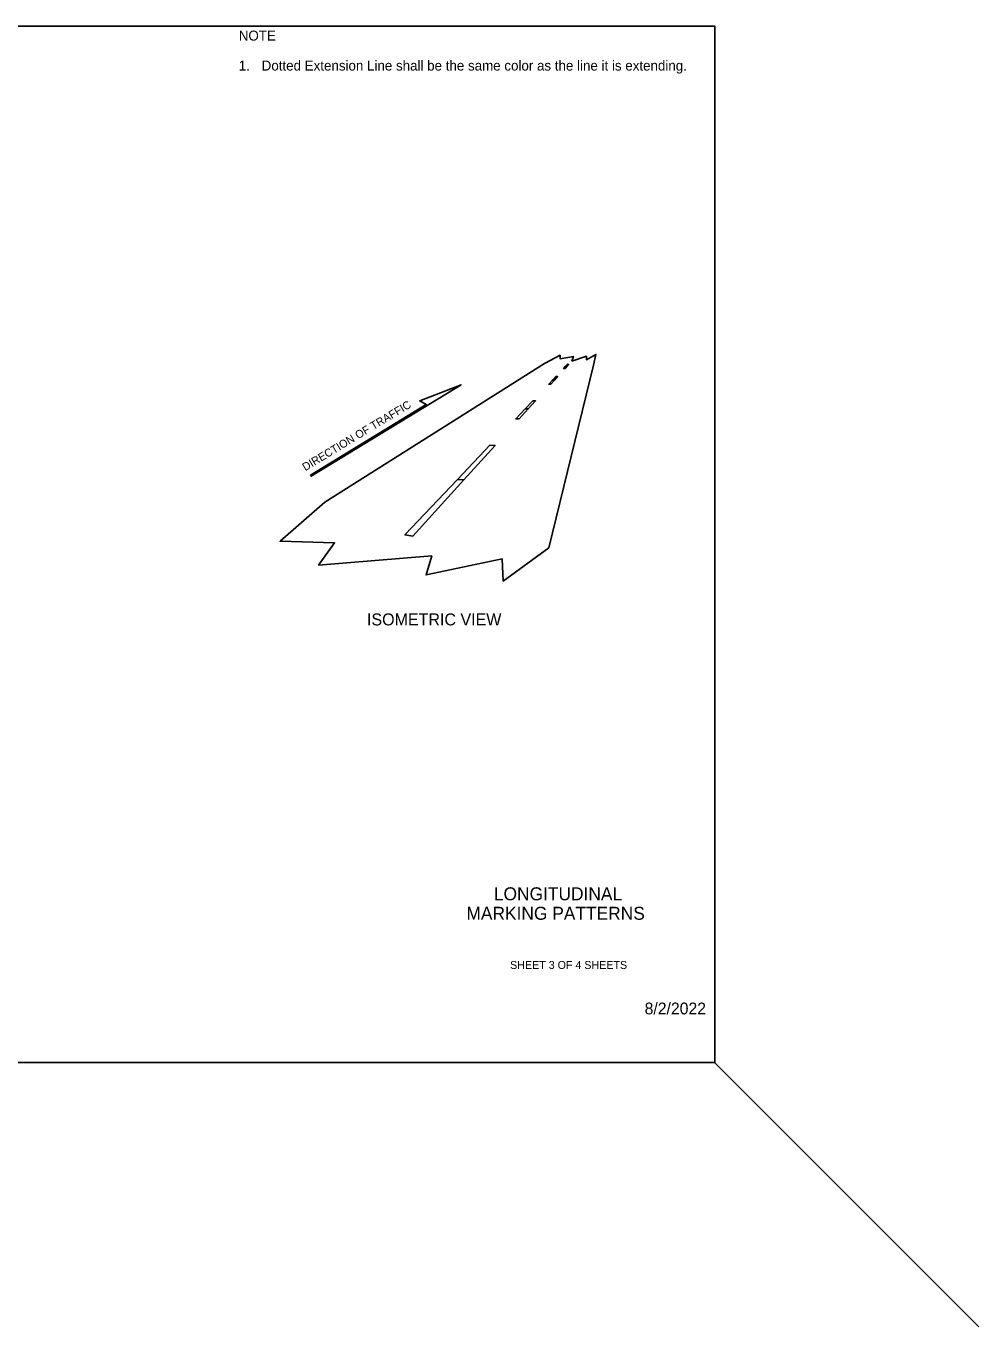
# Model space of a CAD drawing. Extents: x 99754 to 103681, y 99470 to 110996.
# Drawn here: x 101772 to 103681, y 105345 to 107951 of the extents above; entities that cross this region are included whole.
import ezdxf

# ---------------------------------------------------------------- set-up
doc = ezdxf.new("R2010")
doc.units = 0
for name, color, linetype in [('Level 1', 7, 'Continuous'), ('Level 12', 7, 'Continuous'), ('Level 14', 7, 'Continuous'), ('Level 15', 7, 'Continuous'), ('Level 16', 7, 'Continuous'), ('Level 20', 7, 'Continuous'), ('Level 23', 7, 'Continuous'), ('Level 4', 7, 'Continuous'), ('Level 60', 7, 'Continuous'), ('Level 62', 7, 'Continuous')]:
    doc.layers.add(name, color=color, linetype=linetype)

msp = doc.modelspace()

# ---------------------------------------------------------------- linework, layer by layer
at = {"layer": 'Level 1'}
msp.add_line((103151, 105875.5), (103681.3, 105345.2), dxfattribs=at)
msp.add_line((103151, 105875.5), (103681.3, 105345.2), dxfattribs=at)
msp.add_lwpolyline([(99863, 105875), (103152, 105875), (103152, 107951), (99863, 107951)], close=True, dxfattribs=at)
at = {"layer": 'Level 12'}
for p, q in [((102371, 106997.2), (102811.2, 107274.7)), ((102371, 106997.2), (102811.2, 107274.7)), ((102819.5, 106905.6), (102909, 107272)), ((102819.5, 106905.6), (102909, 107272))]:
    msp.add_line(p, q, dxfattribs=at)
at = {"layer": 'Level 14'}
for points in [[(102856.1, 107269.4), (102853.1, 107269.5), (102856.8, 107273.4), (102859.6, 107273.3), (102856.1, 107269.4)], [(102856.1, 107269.4), (102853.1, 107269.5), (102856.8, 107273.4), (102859.6, 107273.3), (102856.1, 107269.4)], [(102856.1, 107269.4), (102853.1, 107269.5), (102856.8, 107273.4), (102859.6, 107273.3), (102856.1, 107269.4)], [(102856.1, 107269.4), (102853.1, 107269.5), (102856.8, 107273.4), (102859.6, 107273.3), (102856.1, 107269.4)], [(102830.9, 107241.7), (102826.9, 107241.8), (102833.5, 107248.8), (102837.2, 107248.7), (102830.9, 107241.7)], [(102830.9, 107241.7), (102826.9, 107241.8), (102833.5, 107248.8), (102837.2, 107248.7), (102830.9, 107241.7)], [(102830.9, 107241.7), (102826.9, 107241.8), (102833.5, 107248.8), (102837.2, 107248.7), (102830.9, 107241.7)], [(102830.9, 107241.7), (102826.9, 107241.8), (102833.5, 107248.8), (102837.2, 107248.7), (102830.9, 107241.7)], [(102778.3, 107183.9), (102772.3, 107184.2), (102787.5, 107200.2), (102793, 107200), (102778.3, 107183.9)], [(102778.3, 107183.9), (102772.3, 107184.2), (102787.5, 107200.2), (102793, 107200), (102778.3, 107183.9)], [(102778.3, 107183.9), (102772.3, 107184.2), (102787.5, 107200.2), (102793, 107200), (102778.3, 107183.9)], [(102778.3, 107183.9), (102772.3, 107184.2), (102787.5, 107200.2), (102793, 107200), (102778.3, 107183.9)], [(102649.1, 107041.7), (102636.6, 107043), (102701.6, 107111.6), (102711.9, 107110.8), (102649.1, 107041.7)], [(102649.1, 107041.7), (102636.6, 107043), (102701.6, 107111.6), (102711.9, 107110.8), (102649.1, 107041.7)], [(102649.1, 107041.7), (102636.6, 107043), (102701.6, 107111.6), (102711.9, 107110.8), (102649.1, 107041.7)], [(102649.1, 107041.7), (102636.6, 107043), (102701.6, 107111.6), (102711.9, 107110.8), (102649.1, 107041.7)]]:
    msp.add_lwpolyline(points, dxfattribs=at)
at = {"layer": 'Level 16'}
for points in [[(102852.1, 107265.1), (102849, 107265.2), (102853.1, 107269.5), (102856.1, 107269.4), (102852.1, 107265.1)], [(102852.1, 107265.1), (102849, 107265.2), (102853.1, 107269.5), (102856.1, 107269.4), (102852.1, 107265.1)], [(102823.5, 107233.6), (102819.3, 107233.8), (102826.9, 107241.8), (102830.9, 107241.7), (102823.5, 107233.6)], [(102823.5, 107233.6), (102819.3, 107233.8), (102826.9, 107241.8), (102830.9, 107241.7), (102823.5, 107233.6)], [(102760.1, 107163.9), (102753.4, 107164.2), (102772.3, 107184.2), (102778.3, 107183.9), (102760.1, 107163.9)], [(102760.1, 107163.9), (102753.4, 107164.2), (102772.3, 107184.2), (102778.3, 107183.9), (102760.1, 107163.9)], [(102547.1, 106929.5), (102531.3, 106931.8), (102636.6, 107043), (102649.1, 107041.7), (102547.1, 106929.5)], [(102547.1, 106929.5), (102531.3, 106931.8), (102636.6, 107043), (102649.1, 107041.7), (102547.1, 106929.5)]]:
    msp.add_lwpolyline(points, dxfattribs=at)
at = {"layer": 'Level 20'}
msp.add_lwpolyline([(102342.4, 107051.3), (102574.1, 107193), (102561, 107200.1), (102643.7, 107232.6), (102343.7, 107049.2)], close=True, dxfattribs=at)
at = {"layer": 'Level 23'}
for p, q in [((102856.1, 107269.4), (102853.1, 107269.5)), ((102853.1, 107269.5), (102856.1, 107269.4)), ((102856.1, 107269.4), (102853.1, 107269.5)), ((102853.1, 107269.5), (102856.1, 107269.4)), ((102826.9, 107241.8), (102833.5, 107248.8)), ((102826.9, 107241.8), (102833.5, 107248.8)), ((102830.9, 107241.7), (102826.9, 107241.8)), ((102826.9, 107241.8), (102830.9, 107241.7)), ((102830.9, 107241.7), (102826.9, 107241.8)), ((102826.9, 107241.8), (102830.9, 107241.7)), ((102778.3, 107183.9), (102772.3, 107184.2)), ((102772.3, 107184.2), (102778.3, 107183.9)), ((102778.3, 107183.9), (102772.3, 107184.2)), ((102772.3, 107184.2), (102778.3, 107183.9)), ((102636.6, 107043), (102649.1, 107041.7)), ((102636.6, 107043), (102649.1, 107041.7))]:
    msp.add_line(p, q, dxfattribs=at)
for points in [[(102856.1, 107269.4), (102852.1, 107265.1), (102849, 107265.2), (102853.1, 107269.5)], [(102856.1, 107269.4), (102852.1, 107265.1), (102849, 107265.2), (102853.1, 107269.5)], [(102853.1, 107269.5), (102856.8, 107273.4), (102859.6, 107273.3), (102856.1, 107269.4)], [(102853.1, 107269.5), (102856.8, 107273.4), (102859.6, 107273.3), (102856.1, 107269.4)], [(102830.9, 107241.7), (102823.5, 107233.6), (102819.3, 107233.8), (102826.9, 107241.8)], [(102830.9, 107241.7), (102823.5, 107233.6), (102819.3, 107233.8), (102826.9, 107241.8)], [(102833.5, 107248.8), (102837.2, 107248.7), (102830.9, 107241.7)], [(102833.5, 107248.8), (102837.2, 107248.7), (102830.9, 107241.7)], [(102778.3, 107183.9), (102760.1, 107163.9), (102753.4, 107164.2), (102772.3, 107184.2)], [(102778.3, 107183.9), (102760.1, 107163.9), (102753.4, 107164.2), (102772.3, 107184.2)], [(102772.3, 107184.2), (102787.5, 107200.2), (102793, 107200), (102778.3, 107183.9)], [(102772.3, 107184.2), (102787.5, 107200.2), (102793, 107200), (102778.3, 107183.9)], [(102649.1, 107041.7), (102636.6, 107043), (102701.6, 107111.6), (102711.9, 107110.8), (102649.1, 107041.7)], [(102649.1, 107041.7), (102636.6, 107043), (102701.6, 107111.6), (102711.9, 107110.8), (102649.1, 107041.7)], [(102649.1, 107041.7), (102547.1, 106929.5), (102531.3, 106931.8), (102636.6, 107043)], [(102649.1, 107041.7), (102547.1, 106929.5), (102531.3, 106931.8), (102636.6, 107043)]]:
    msp.add_lwpolyline(points, dxfattribs=at)
at = {"layer": 'Level 4'}
msp.add_line((102909, 107272), (102819.5, 106905.6), dxfattribs=at)
msp.add_line((102909, 107272), (102819.5, 106905.6), dxfattribs=at)
for points in [[(102909, 107272), (102913.9, 107293.2), (102894.9, 107282.4), (102894.8, 107289.7), (102865.7, 107280), (102868.9, 107289.3), (102842.1, 107284.7), (102842.2, 107291.5), (102811.2, 107274.7)], [(102811.2, 107274.7), (102842.2, 107291.5), (102842.1, 107284.7), (102868.9, 107289.3), (102865.7, 107280), (102894.8, 107289.7), (102894.9, 107282.4), (102913.9, 107293.2), (102909, 107272)], [(102909, 107272), (102913.9, 107293.2), (102894.9, 107282.4), (102894.8, 107289.7), (102865.7, 107280), (102868.9, 107289.3), (102842.1, 107284.7), (102842.2, 107291.5), (102811.2, 107274.7)], [(102811.2, 107274.7), (102842.2, 107291.5), (102842.1, 107284.7), (102868.9, 107289.3), (102865.7, 107280), (102894.8, 107289.7), (102894.9, 107282.4), (102913.9, 107293.2), (102909, 107272)], [(102819.5, 106905.6), (102728.4, 106839.1), (102726.4, 106883.5), (102573.8, 106851.5), (102585.1, 106889.7), (102358.3, 106871.1), (102390.3, 106915.5), (102281, 106919.1), (102371, 106997.2), (102811.2, 107274.7)], [(102819.5, 106905.6), (102728.4, 106839.1), (102726.4, 106883.5), (102573.8, 106851.5), (102585.1, 106889.7), (102358.3, 106871.1), (102390.3, 106915.5), (102281, 106919.1), (102371, 106997.2), (102811.2, 107274.7)], [(102819.5, 106905.6), (102728.4, 106839.1), (102726.4, 106883.5), (102573.8, 106851.5), (102585.1, 106889.7), (102358.3, 106871.1), (102390.3, 106915.5), (102281, 106919.1), (102371, 106997.2), (102811.2, 107274.7)], [(102819.5, 106905.6), (102728.4, 106839.1), (102726.4, 106883.5), (102573.8, 106851.5), (102585.1, 106889.7), (102358.3, 106871.1), (102390.3, 106915.5), (102281, 106919.1), (102371, 106997.2), (102811.2, 107274.7)], [(102909, 107272), (102909, 107272), (102819.5, 106905.6)], [(102909, 107272), (102909, 107272), (102819.5, 106905.6)]]:
    msp.add_lwpolyline(points, dxfattribs=at)
at = {"layer": 'Level 60'}
msp.add_line((103152, 107951), (103152, 107951), dxfattribs=at)

# ---------------------------------------------------------------- texts
at = {"layer": 'Level 15'}
msp.add_text('8/2/2022', height=23.62, dxfattribs=at).set_placement((103011.5, 105971.3))
at = {"layer": 'Level 20'}
for s, height, p in [('NOTE', 20, (102198.4, 107921.8)), ('1.', 20, (102198.4, 107861.8)), ('Dotted Extension Line shall be the same color as the line it is extending. ', 20, (102244.3, 107861.8)), ('ISOMETRIC VIEW', 24, (102455.3, 106750.4))]:
    msp.add_text(s, height=height, dxfattribs=at).set_placement(p)
msp.add_text('DIRECTION OF TRAFFIC', height=16, rotation=31.1288, dxfattribs=at).set_placement((102331.7, 107059.1))
at = {"layer": 'Level 62'}
for s, height, p in [('LONGITUDINAL ', 26, (102709.5, 106199.8)), ('MARKING PATTERNS', 26, (102654.5, 106160.8)), ('SHEET 3 OF 4 SHEETS', 16, (102742.1, 106062.3))]:
    msp.add_text(s, height=height, dxfattribs=at).set_placement(p)

doc.saveas('drawing.dxf')
